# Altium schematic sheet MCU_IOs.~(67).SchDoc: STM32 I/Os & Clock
size A4; Date: Not used; ApprovedBy: Not used; CheckedBy: Not used; Author: Not used; CompanyName: STMicroelectronics; DrawnBy: Not used; Engineer: Not used; Organization: Not used; Address1: Not used; Address2: Not used; Address3: Not used; Address4: Not used; DocumentNumber: 3; Revision: Not used; SheetNumber: 3; SheetTotal: 5
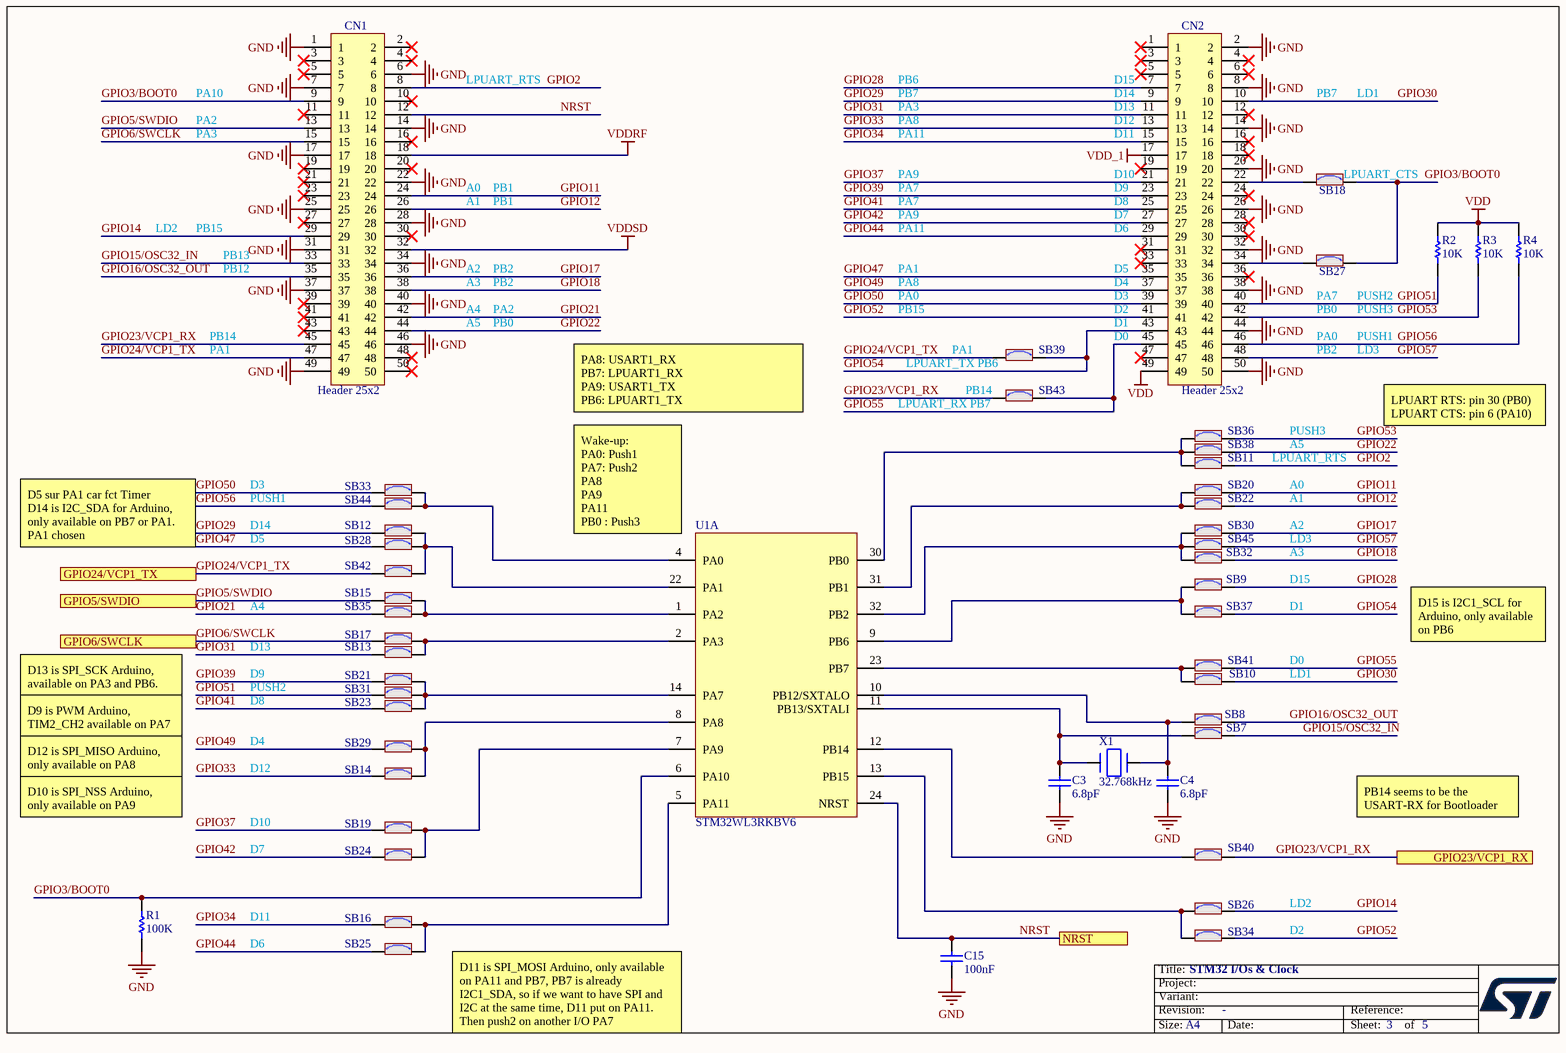
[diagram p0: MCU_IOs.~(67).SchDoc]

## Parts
C3  value 6.8pF  [C0402]  (hidden comment: Capacitor)
C4  value 6.8pF  [C0402]  (hidden comment: Capacitor)
C15  value 100nF  [C0402]  (hidden comment: Capacitor)
CN1  Header 25x2  [CON_SAMTEC_FTSH-125-02-L-DV]
CN2  Header 25x2  [CON_SAMTEC_FTSH-125-02-L-DV]
R1  value 100K  [R0402]  (hidden comment: Resistor)
R2  value 10K  [R0402]  (hidden comment: Resistor)
R3  value 10K  [R0402]  (hidden comment: Resistor)
R4  value 10K  [R0402]  (hidden comment: Resistor)
SB7  SB_ON  [SOLDER-BRIDGE_R0402-0R]  (value not drawn)
SB8  SB_ON  [SOLDER-BRIDGE_R0402-0R]  (value not drawn)
SB9  SB_ON  [SOLDER-BRIDGE_R0402-0R]  (value not drawn)
SB10  SB_ON  [SOLDER-BRIDGE_R0402-0R]  (value not drawn)
SB11  SB_ON  [SOLDER-BRIDGE_R0402-0R]  (value not drawn)
SB12  SB_ON  [SOLDER-BRIDGE_R0402-0R]  (value not drawn)
SB13  SB_ON  [SOLDER-BRIDGE_R0402-0R]  (value not drawn)
SB14  SB_ON  [SOLDER-BRIDGE_R0402-0R]  (value not drawn)
SB15  SB_ON  [SOLDER-BRIDGE_R0402-0R]  (value not drawn)
SB16  SB_ON  [SOLDER-BRIDGE_R0402-0R]  (value not drawn)
SB17  SB_ON  [SOLDER-BRIDGE_R0402-0R]  (value not drawn)
SB18  SB_ON  [SOLDER-BRIDGE_R0402-0R]  (value not drawn)
SB19  SB_ON  [SOLDER-BRIDGE_R0402-0R]  (value not drawn)
SB20  SB_ON  [SOLDER-BRIDGE_R0402-0R]  (value not drawn)
SB21  SB_ON  [SOLDER-BRIDGE_R0402-0R]  (value not drawn)
SB22  SB_ON  [SOLDER-BRIDGE_R0402-0R]  (value not drawn)
SB23  SB_ON  [SOLDER-BRIDGE_R0402-0R]  (value not drawn)
SB24  SB_ON  [SOLDER-BRIDGE_R0402-0R]  (value not drawn)
SB25  SB_ON  [SOLDER-BRIDGE_R0402-0R]  (value not drawn)
SB26  SB_ON  [SOLDER-BRIDGE_R0402-0R]  (value not drawn)
SB27  SB_ON  [SOLDER-BRIDGE_R0402-0R]  (value not drawn)
SB28  SB_ON  [SOLDER-BRIDGE_R0402-0R]  (value not drawn)
SB29  SB_ON  [SOLDER-BRIDGE_R0402-0R]  (value not drawn)
SB30  SB_ON  [SOLDER-BRIDGE_R0402-0R]  (value not drawn)
SB31  SB_ON  [SOLDER-BRIDGE_R0402-0R]  (value not drawn)
SB32  SB_ON  [SOLDER-BRIDGE_R0402-0R]  (value not drawn)
SB33  SB_ON  [SOLDER-BRIDGE_R0402-0R]  (value not drawn)
SB34  SB_ON  [SOLDER-BRIDGE_R0402-0R]  (value not drawn)
SB35  SB_ON  [SOLDER-BRIDGE_R0402-0R]  (value not drawn)
SB36  SB_ON  [SOLDER-BRIDGE_R0402-0R]  (value not drawn)
SB37  SB_ON  [SOLDER-BRIDGE_R0402-0R]  (value not drawn)
SB38  SB_ON  [SOLDER-BRIDGE_R0402-0R]  (value not drawn)
SB39  SB_ON  [SOLDER-BRIDGE_R0402-0R]  (value not drawn)
SB40  SB_ON  [SOLDER-BRIDGE_R0402-0R]  (value not drawn)
SB41  SB_ON  [SOLDER-BRIDGE_R0402-0R]  (value not drawn)
SB42  SB_ON  [SOLDER-BRIDGE_R0402-0R]  (value not drawn)
SB43  SB_ON  [SOLDER-BRIDGE_R0402-0R]  (value not drawn)
SB44  SB_ON  [SOLDER-BRIDGE_R0402-0R]  (value not drawn)
SB45  SB_ON  [SOLDER-BRIDGE_R0402-0R]  (value not drawn)
U1  value STM32WL3RKBV6  [ICC_VFQFPN32-EPAD_5X5_P050]  (hidden comment: IC_STM32WL3R)  (part A of 3)
X1  value 32.768kHz  [CRY_NX2012SA_2P]  (hidden comment: XTAL_2_PINS)

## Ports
GPIO5/SWDIO, GPIO6/SWCLK, GPIO23/VCP1_RX, GPIO24/VCP1_TX, NRST

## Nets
GND: C3.1 C4.2 C15.1 CN1.1 CN1.6 CN1.7 CN1.14 CN1.17 CN1.22 CN1.25 CN1.28 CN1.31 CN1.34 CN1.37 CN1.40 CN1.46 CN1.49 CN2.2 CN2.8 CN2.14 CN2.20 CN2.26 CN2.32 CN2.38 CN2.44 CN2.50 R1.1
VDD: CN2.49 R2.2 R3.2 R4.2
VDD_1: CN2.17
VDDRF: CN1.18
VDDSD: CN1.32
GPIO2: CN1.8 SB11.2
GPIO3/BOOT0: CN1.9 R1.2 SB18.2 SB27.2 U1.6(PA10)
GPIO5/SWDIO: CN1.13 SB15.1 ; port GPIO5/SWDIO
GPIO6/SWCLK: CN1.15 SB17.1 ; port GPIO6/SWCLK
GPIO11: CN1.24 SB20.2
GPIO12: CN1.26 SB22.2
GPIO14: CN1.29 SB26.2
GPIO15/OSC32_IN: CN1.33 SB7.2
GPIO16/OSC32_OUT: CN1.35 SB8.2
GPIO17: CN1.36 SB30.2
GPIO18: CN1.38 SB32.2
GPIO21: CN1.42 SB35.1
GPIO22: CN1.44 SB38.2
GPIO23/VCP1_RX: CN1.45 SB40.2 SB43.1 ; port GPIO23/VCP1_RX
GPIO24/VCP1_TX: CN1.47 SB39.1 SB42.1 ; port GPIO24/VCP1_TX
GPIO28: CN2.7 SB9.2
GPIO29: CN2.9 SB12.1
GPIO30: CN2.10 SB10.2
GPIO31: CN2.11 SB13.1
GPIO33: CN2.13 SB14.1
GPIO34: CN2.15 SB16.1
GPIO37: CN2.21 SB19.1
GPIO39: CN2.23 SB21.1
GPIO41: CN2.25 SB23.1
GPIO42: CN2.27 SB24.1
GPIO44: CN2.29 SB25.1
GPIO47: CN2.35 SB28.1
GPIO49: CN2.37 SB29.1
GPIO50: CN2.39 SB33.1
GPIO51: CN2.40 R2.1 SB31.1
GPIO52: CN2.41 SB34.2
GPIO53: CN2.42 R3.1 SB36.2
GPIO54: CN2.43 SB37.2 SB39.2
GPIO55: CN2.45 SB41.2 SB43.2
GPIO56: CN2.46 R4.1 SB44.1
GPIO57: CN2.48 SB45.2
NRST: C15.2 CN1.12 U1.24(NRST) ; port NRST
NetC3_2: C3.2 SB7.1 U1.11(PB13/SXTALI) X1.1(X1)
NetC4_1: C4.1 SB8.1 U1.10(PB12/SXTALO) X1.2(X2)
NetCN2_22: CN2.22 SB18.1
NetCN2_34: CN2.34 SB27.1
NetSB9_1: SB9.1 SB37.1 U1.9(PB6)
NetSB10_1: SB10.1 SB41.1 U1.23(PB7)
NetSB11_1: SB11.1 SB36.1 SB38.1 U1.30(PB0)
NetSB12_2: SB12.2 SB28.2 SB42.2 U1.22(PA1)
NetSB13_2: SB13.2 SB17.2 U1.2(PA3)
NetSB14_2: SB14.2 SB29.2 U1.8(PA8)
NetSB15_2: SB15.2 SB35.2 U1.1(PA2)
NetSB16_2: SB16.2 SB25.2 U1.5(PA11)
NetSB19_2: SB19.2 SB24.2 U1.7(PA9)
NetSB20_1: SB20.1 SB22.1 U1.31(PB1)
NetSB21_2: SB21.2 SB23.2 SB31.2 U1.14(PA7)
NetSB26_1: SB26.1 SB34.1 U1.13(PB15)
NetSB30_1: SB30.1 SB32.1 SB45.1 U1.32(PB2)
NetSB33_2: SB33.2 SB44.2 U1.4(PA0)
NetSB40_1: SB40.1 U1.12(PB14)

Not connected (* = marked no-connect by the designer): CN1 2* 3* 4* 5* 10* 11* 16* 19* 20* 21* 23* 27* 30* 39* 41* 43* 48* 50*; CN2 1* 3* 4* 5* 6* 12* 16* 18* 19* 24* 28* 30* 31* 33* 36* 47*

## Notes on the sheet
- PA10
- LPUART_RTS
- PB7
- PB6
- PA3
- (near CN2) D13
- (near CN2) D14
- (near CN2) D15
- LD1
- PA2
- PA8
- PA11
- PA9
- (near CN2) D11
- (near CN2) D12
- (near CN2) D10
- (near SB18) LPUART_CTS
- LD2
- PB15
- A0
- A1
- PB1
- PA7
- (near CN2) D9
- (near CN2) D8
- (near CN2) D7
- (near CN2) D6
- PB13
- PB12
- A4
- A3
- A2
- PB2
- PA1
- PA0
- (near CN2) D5
- (near CN2) D4
- (near CN2) D3
- (near CN2) D2
- (near SB27) PA7
- (near SB27) PB0
- (near SB27) PUSH2
- PUSH3
- PB14
- A5
- PB0
- LPUART_TX PB6
- (near CN2) D1
- (near CN2) D0
- LD3
- PUSH1
- PA8: USART1_RX
  PB7: LPUART1_RX
  PA9: USART1_TX
  PB6: LPUART1_TX
- (near SB43) LPUART_RX PB7
- (near SB43) PB14
- LPUART RTS: pin 30 (PB0)
  LPUART CTS: pin 6 (PA10)
- D3
- D5 sur PA1 car fct Timer
  D14 is I2C_SDA for Arduino, only available on PB7 or PA1.
  PA1 chosen
- D14
- D5
- (near U1) Wake-up:
  PA0: Push1
  PA7: Push2
  PA8
  PA9
  PA11
  PB0 : Push3
- D15
- D13
- D1
- D15 is I2C1_SCL for Arduino, only available on PB6
- D13 is SPI_SCK Arduino,  available on PA3 and PB6. PA3 chosen
- D8
- PUSH2
- D9
- D0
- D12 is SPI_MISO Arduino, only available on PA8
- D9 is PWM Arduino,  TIM2_CH2 available on PA7
- D4
- D12
- D10 is SPI_NSS Arduino, only available on PA9
- D7
- D10
- PB14 seems to be the USART-RX for Bootloader
- D11
- D6
- D2
- D11 is SPI_MOSI Arduino, only available on PA11 and PB7, PB7 is already I2C1_SDA, so if we want to have SPI and I2C at the same time, D11 put on PA11. Then push2 on another I/O PA7

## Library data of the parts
C3 C4 = MCD-03452: Capacitor, MLCC, 6.8pF, 50V,C0G/NP0, +/-0.05pF, 0402, T=0.5mm; Part_Preference: Recommended; Manufacturer: MURATA; Manufacturer_Part_Number: GJM1555C1H6R8WB01; ShowFields: YES; ID: 5568; Component_Country_Of_Origin: Japan, Singapore
C15 = MCD-00006: Capacitor, MLCC, 100nF, 16V, X7R, +/-10%, 0402, T=0.5mm; Manufacturer_Part_Number: CC0402KRX7R7BB104; Manufacturer: YAGEO; Part_Preference: Recommended; Partial_Alternate_Internal_Part_Number: MCD-03299; Order_Code_RS: 9402047; Component_Country_Of_Origin: China; ShowFields: YES; ID: 2474
CN1 CN2 = MCD-02746: Header, 25x2, 1.27mm, VR, SMD, T=4.83mm; Part_Type: Connector; Part_Preference: Recommended; Manufacturer: SAMTEC; Manufacturer_Part_Number: FTSH-125-02-L-DV; Partial_Alternate_Internal_Part_Number: MCD-03741; ShowFields: YES; ID: 4858; Component_Country_Of_Origin: China, Costa Rica, Malaysia, USA, Vietnam
R1 = MCD-00059: Resistor, 100K, 0402, +/-1%, 1/16W; Part_Preference: Recommended; Manufacturer: YAGEO; Manufacturer_Part_Number: RC0402FR-07100KL; Partial_Alternate_Internal_Part_Number: MCD-03301; Order_Code_RS: 2421891; ShowFields: YES; ID: 2533; Component_Country_Of_Origin: China
R2-R4 = MCD-00053: Resistor, 10K, 0402, +/-1%, 1/16W; BMS_Part_Number: 9131590; Part_Preference: Recommended; Manufacturer: YAGEO; Manufacturer_Part_Number: RC0402FR-0710KL; Order_Code_RS: 9239359; Component_Country_Of_Origin: China; ShowFields: YES; ID: 2539
SB7-SB45 = MCD-01618: Resistor, 0R, SB0402, 5%, 0.063W; Part_Preference: Recommended; Manufacturer: YAGEO; Manufacturer_Part_Number: RC0402JR-070RL; Order_Code_RS: 618-5804; Component_Country_Of_Origin: China; ShowFields: YES; ID: 3718
U1 = MCD-04431: MCU, ARM Cortex-M0 32-bit, 128KB Flash, 16KB SRAM, With Crypto; Part_Type: IC; Part_Preference: Recommended; Manufacturer: STMICROELECTRONICS; ShowFields: YES; ID: 6547; Component_Country_Of_Origin: Unknown
X1 = MCD-01445: Crystal, 32.768kHz, 7pF, +/-20ppm, 80K, 2.05x1.2mm; BMS_Part_Number: 9157043; Part_Type: Crystal_Osc; Part_Preference: Recommended; Manufacturer: NDK; Manufacturer_Part_Number: NX2012SA-32.768KHz-EXS00A-MU00389; Component_Country_Of_Origin: Japan; ShowFields: YES; ID: 3545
